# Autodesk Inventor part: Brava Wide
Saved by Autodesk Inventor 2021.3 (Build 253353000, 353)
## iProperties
Created: 2022-09
Part Number: Brava Wide
Material: Generic
Document SubType Name: Modeling
Designer: Administrator
Density: 1 g/cm^3
Appearance: Default
Title: Brava Wide
Author: Administrator
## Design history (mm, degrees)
feature "Glass-Brava Wide_"
body "Solid1"
